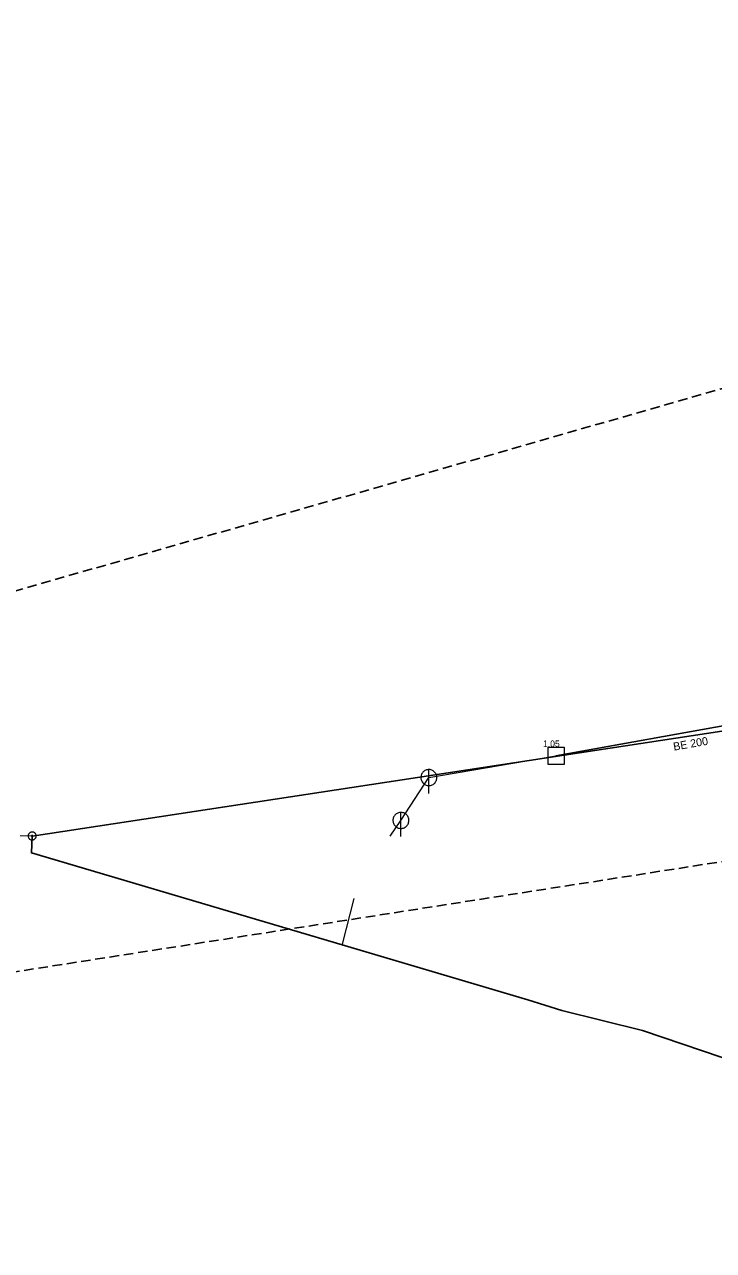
# Model space of a CAD drawing. Extents: x -689820 to -689363, y -975369 to -975062.
# Drawn here: x -689714.8 to -689628.7, y -975368.9 to -975215.7 of the extents above; entities that cross this region are included whole.
import ezdxf

# ---------------------------------------------------------------- set-up
doc = ezdxf.new("R2010")
doc.units = 0
doc.header["$LTSCALE"] = 0.4
doc.linetypes.add('MEDIUM_DASHED', pattern=[4.5, 3, -1.5])
doc.layers.add('1', color=7, linetype='Continuous')
for name, color, linetype, lineweight in [('11', 7, 'Continuous', 13), ('13', 7, 'Continuous', 13), ('14', 7, 'Continuous', 25), ('17', 7, 'Continuous', 25), ('22', 7, 'Continuous', 13), ('47', 7, 'Continuous', 13), ('63', 7, 'MEDIUM_DASHED', 25)]:
    doc.layers.add(name, color=color, linetype=linetype, lineweight=lineweight)

msp = doc.modelspace()

# ---------------------------------------------------------------- linework, layer by layer
at = {"layer": '11'}
msp.add_lwpolyline([(-689669.152, -975317.152), (-689667.803, -975315.167), (-689664.31, -975309.809), (-689648.44, -975307.089)], dxfattribs=at)
at = {"layer": '13'}
msp.add_line((-689675.111, -975330.61), (-689673.637, -975324.93), dxfattribs=at)
at = {"layer": '14'}
msp.add_line((-689648.44, -975307.089), (-689613.713, -975300.842), dxfattribs=at)
at = {"layer": '14', "lineweight": 13}
msp.add_line((-689713.89, -975317.113), (-689715.37, -975317.07), dxfattribs=at)
at = {"layer": '17'}
for points in [[(-689536.351, -975289.602), (-689537.203, -975289.743), (-689537.12, -975290.232), (-689713.89, -975317.113)], [(-689546.18, -975368.915), (-689546.615, -975368.909), (-689556.942, -975368.745), (-689575.305, -975362.528), (-689637.592, -975341.438), (-689647.677, -975338.907), (-689651.947, -975337.591), (-689675.142, -975330.715), (-689713.978, -975319.23), (-689713.89, -975317.113)]]:
    msp.add_lwpolyline(points, dxfattribs=at)
at = {"layer": '22'}
for p, q in [((-689664.31, -975311.809), (-689664.309, -975308.809)), ((-689667.803, -975317.167), (-689667.802, -975314.167))]:
    msp.add_line(p, q, dxfattribs=at)
for points in [[(-689649.419, -975305.999), (-689647.387, -975305.999), (-689647.387, -975308.192), (-689649.419, -975308.192)], [(-689663.31, -975309.809), (-689663.315, -975309.7), (-689663.333, -975309.592), (-689663.363, -975309.486), (-689663.403, -975309.385), (-689663.455, -975309.288), (-689663.517, -975309.198), (-689663.589, -975309.115), (-689663.669, -975309.041), (-689663.757, -975308.975), (-689663.851, -975308.92), (-689663.951, -975308.875), (-689664.056, -975308.842), (-689664.163, -975308.82), (-689664.272, -975308.81), (-689664.382, -975308.812), (-689664.49, -975308.826), (-689664.597, -975308.851), (-689664.7, -975308.888), (-689664.798, -975308.937), (-689664.89, -975308.995), (-689664.976, -975309.064), (-689665.053, -975309.141), (-689665.122, -975309.227), (-689665.181, -975309.319), (-689665.229, -975309.417), (-689665.266, -975309.52), (-689665.292, -975309.627), (-689665.306, -975309.735), (-689665.309, -975309.845), (-689665.299, -975309.954), (-689665.278, -975310.061), (-689665.244, -975310.165), (-689665.2, -975310.265), (-689665.145, -975310.36), (-689665.079, -975310.448), (-689665.005, -975310.528), (-689664.922, -975310.6), (-689664.832, -975310.662), (-689664.736, -975310.714), (-689664.634, -975310.755), (-689664.529, -975310.785), (-689664.421, -975310.803), (-689664.311, -975310.809), (-689664.202, -975310.803), (-689664.094, -975310.785), (-689663.989, -975310.756), (-689663.887, -975310.715), (-689663.79, -975310.663), (-689663.7, -975310.601), (-689663.617, -975310.53), (-689663.542, -975310.45), (-689663.477, -975310.362), (-689663.421, -975310.268), (-689663.377, -975310.168), (-689663.343, -975310.064), (-689663.321, -975309.956), (-689663.311, -975309.847)], [(-689666.803, -975315.167), (-689666.808, -975315.058), (-689666.826, -975314.95), (-689666.856, -975314.844), (-689666.896, -975314.743), (-689666.948, -975314.646), (-689667.01, -975314.556), (-689667.082, -975314.473), (-689667.162, -975314.399), (-689667.25, -975314.333), (-689667.344, -975314.278), (-689667.444, -975314.233), (-689667.549, -975314.2), (-689667.656, -975314.178), (-689667.765, -975314.168), (-689667.875, -975314.17), (-689667.983, -975314.184), (-689668.09, -975314.209), (-689668.193, -975314.246), (-689668.291, -975314.295), (-689668.383, -975314.353), (-689668.469, -975314.422), (-689668.546, -975314.499), (-689668.615, -975314.585), (-689668.674, -975314.677), (-689668.722, -975314.775), (-689668.759, -975314.878), (-689668.785, -975314.985), (-689668.799, -975315.093), (-689668.802, -975315.203), (-689668.792, -975315.312), (-689668.771, -975315.419), (-689668.737, -975315.523), (-689668.693, -975315.623), (-689668.638, -975315.718), (-689668.572, -975315.806), (-689668.498, -975315.886), (-689668.415, -975315.958), (-689668.325, -975316.02), (-689668.229, -975316.072), (-689668.127, -975316.113), (-689668.022, -975316.143), (-689667.914, -975316.161), (-689667.804, -975316.167), (-689667.695, -975316.161), (-689667.587, -975316.143), (-689667.482, -975316.114), (-689667.38, -975316.073), (-689667.283, -975316.021), (-689667.193, -975315.959), (-689667.11, -975315.888), (-689667.035, -975315.808), (-689666.97, -975315.72), (-689666.914, -975315.626), (-689666.87, -975315.526), (-689666.836, -975315.422), (-689666.814, -975315.314), (-689666.804, -975315.205)]]:
    msp.add_lwpolyline(points, close=True, dxfattribs=at)
at = {"layer": '47'}
for points in [[(-689713.409, -975317.252), (-689713.398, -975317.201), (-689713.391, -975317.149), (-689713.39, -975317.097), (-689713.394, -975317.045), (-689713.404, -975316.993), (-689713.419, -975316.943), (-689713.44, -975316.895), (-689713.465, -975316.85), (-689713.494, -975316.807), (-689713.528, -975316.767), (-689713.567, -975316.73), (-689713.609, -975316.699), (-689713.653, -975316.672), (-689713.701, -975316.65), (-689713.75, -975316.632), (-689713.801, -975316.621), (-689713.853, -975316.614), (-689713.906, -975316.613), (-689713.957, -975316.617), (-689714.009, -975316.627), (-689714.059, -975316.642), (-689714.107, -975316.663), (-689714.153, -975316.688), (-689714.196, -975316.717), (-689714.235, -975316.751), (-689714.272, -975316.79), (-689714.304, -975316.832), (-689714.33, -975316.876), (-689714.352, -975316.924), (-689714.37, -975316.973), (-689714.381, -975317.024), (-689714.388, -975317.076), (-689714.39, -975317.128), (-689714.385, -975317.18), (-689714.375, -975317.232), (-689714.361, -975317.282), (-689714.34, -975317.33), (-689714.315, -975317.376), (-689714.285, -975317.419), (-689714.251, -975317.458), (-689714.212, -975317.495), (-689714.171, -975317.526), (-689714.126, -975317.553), (-689714.078, -975317.575), (-689714.029, -975317.593), (-689713.978, -975317.604), (-689713.926, -975317.611), (-689713.875, -975317.613), (-689713.822, -975317.608), (-689713.77, -975317.598), (-689713.72, -975317.584), (-689713.673, -975317.563), (-689713.627, -975317.538), (-689713.584, -975317.508), (-689713.544, -975317.474), (-689713.507, -975317.435), (-689713.477, -975317.394), (-689713.449, -975317.349), (-689713.427, -975317.301)], [(-689713.811, -975317.135), (-689713.808, -975317.127), (-689713.808, -975317.119), (-689713.808, -975317.11), (-689713.808, -975317.102), (-689713.81, -975317.093), (-689713.813, -975317.085), (-689713.816, -975317.077), (-689713.82, -975317.069), (-689713.825, -975317.063), (-689713.83, -975317.056), (-689713.837, -975317.05), (-689713.844, -975317.045), (-689713.851, -975317.04), (-689713.858, -975317.036), (-689713.867, -975317.034), (-689713.875, -975317.031), (-689713.883, -975317.031), (-689713.892, -975317.031), (-689713.9, -975317.031), (-689713.909, -975317.033), (-689713.917, -975317.036), (-689713.925, -975317.039), (-689713.933, -975317.043), (-689713.94, -975317.048), (-689713.946, -975317.053), (-689713.952, -975317.06), (-689713.957, -975317.067), (-689713.962, -975317.074), (-689713.966, -975317.081), (-689713.968, -975317.09), (-689713.971, -975317.098), (-689713.971, -975317.106), (-689713.971, -975317.115), (-689713.971, -975317.123), (-689713.969, -975317.132), (-689713.967, -975317.14), (-689713.963, -975317.148), (-689713.959, -975317.156), (-689713.954, -975317.163), (-689713.949, -975317.169), (-689713.942, -975317.175), (-689713.935, -975317.18), (-689713.928, -975317.185), (-689713.921, -975317.189), (-689713.912, -975317.191), (-689713.904, -975317.194), (-689713.896, -975317.194), (-689713.887, -975317.194), (-689713.879, -975317.194), (-689713.87, -975317.192), (-689713.862, -975317.19), (-689713.854, -975317.186), (-689713.846, -975317.182), (-689713.84, -975317.177), (-689713.833, -975317.172), (-689713.827, -975317.165), (-689713.822, -975317.158), (-689713.817, -975317.151), (-689713.813, -975317.144)]]:
    msp.add_lwpolyline(points, close=True, dxfattribs=at)
at = {"layer": '63'}
msp.add_lwpolyline([(-689662.123, -975114.404), (-689588.993, -975102.123), (-689588.993, -975102.123), (-689580.62, -975185.301), (-689580.62, -975185.301), (-689519.213, -975267.921), (-689519.213, -975267.921), (-689394.167, -975240.009), (-689394.167, -975240.009), (-689384.677, -975282.435), (-689384.677, -975282.435), (-689764.282, -975341.609), (-689764.282, -975341.609), (-689752.559, -975296.95), (-689752.559, -975296.95), (-689602.391, -975253.965), (-689627.512, -975210.422), (-689603.508, -975253.965), (-689648.167, -975167.437), (-689648.167, -975167.437)], close=True, dxfattribs=at)

# ---------------------------------------------------------------- texts
at = {"layer": '1'}
msp.add_text('BE 200', height=1, rotation=10, dxfattribs=at).set_placement((-689633.677, -975306.45))
msp.add_text('1,05', height=0.8, dxfattribs=at).set_placement((-689650.039, -975305.973))

doc.saveas('drawing.dxf')
